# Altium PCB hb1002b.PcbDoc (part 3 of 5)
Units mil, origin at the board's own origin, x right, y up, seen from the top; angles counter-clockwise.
Board outline 2756 x 3549 mil, 2 copper layers (Top Layer, Bottom Layer); 120 components, 136 nets, 498 pads, 328 vias.
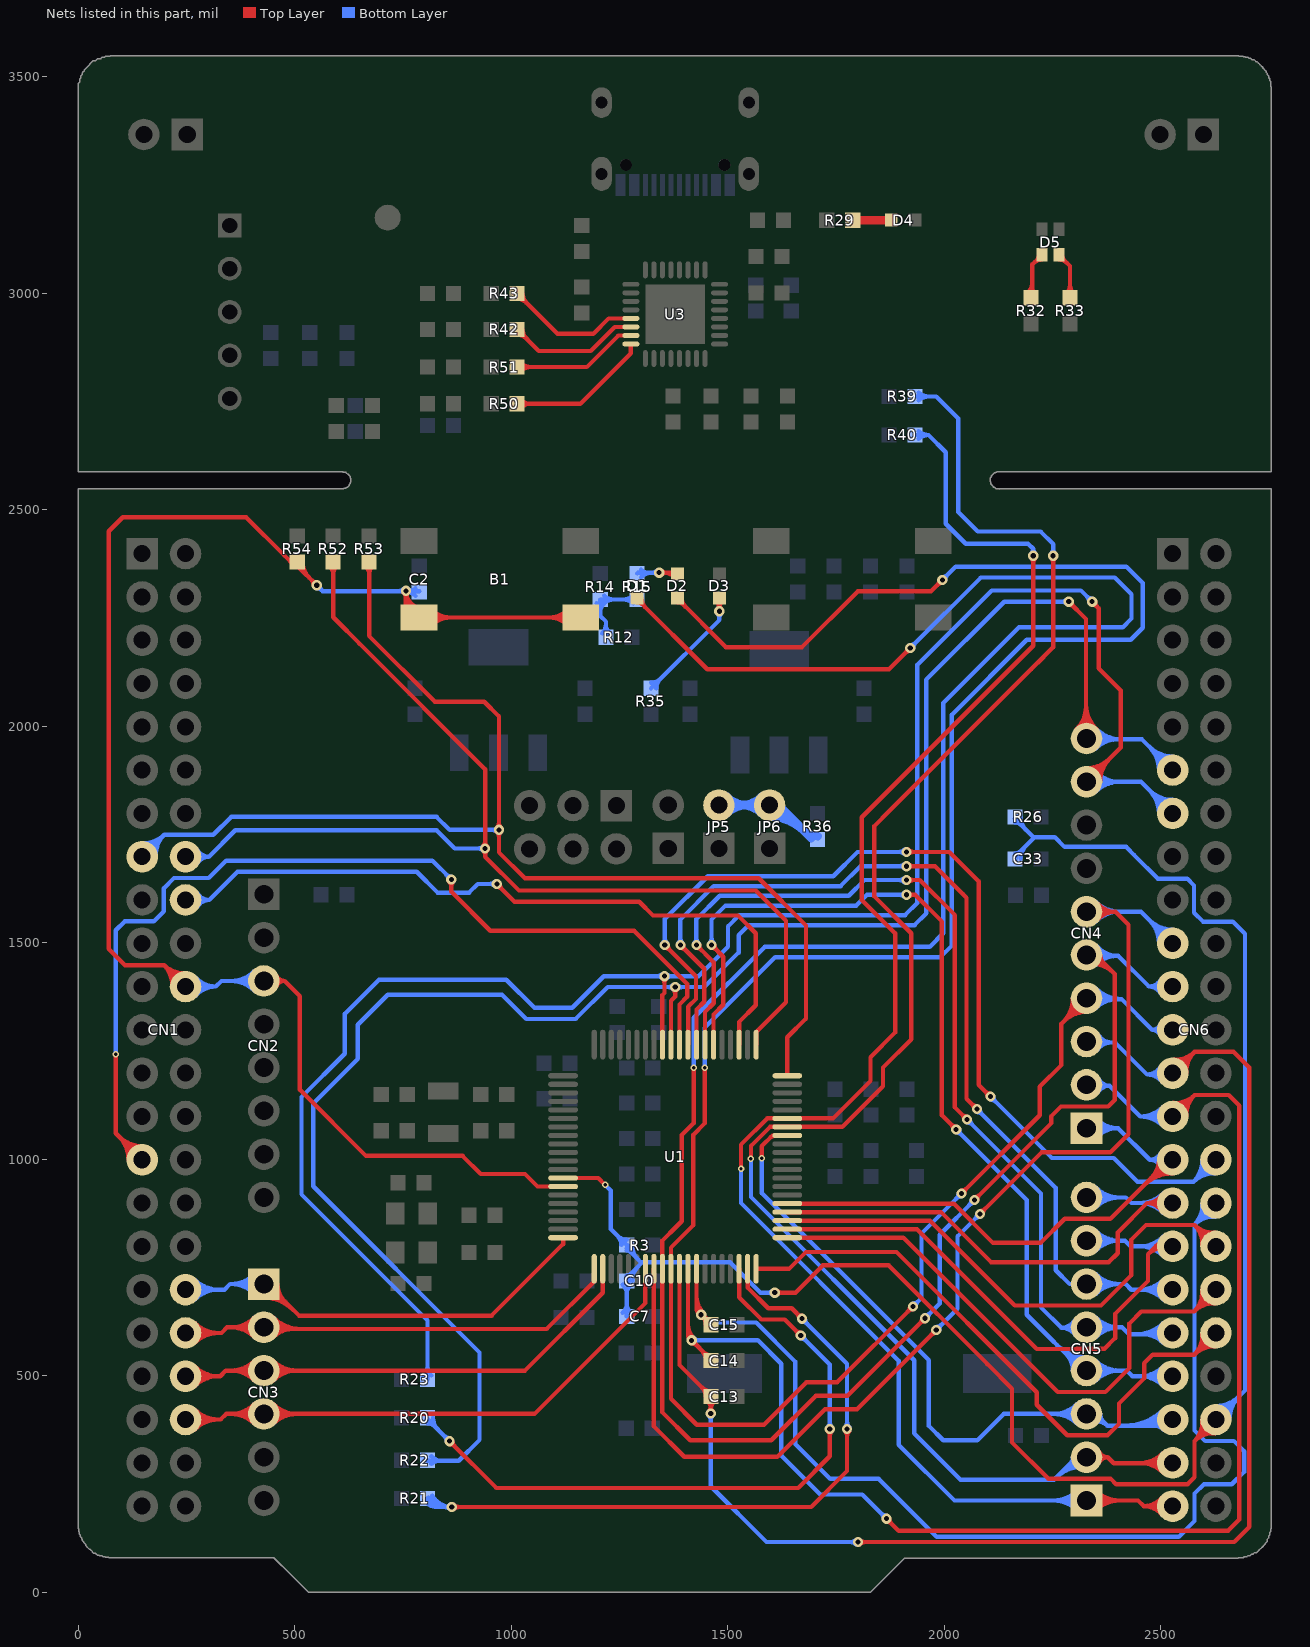
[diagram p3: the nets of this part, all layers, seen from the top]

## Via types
v1: diameter 23.62, hole 11.81, Top Layer to Bottom Layer, tented both sides, 276 vias
v2: diameter 39.37, hole 23.62, Top Layer to Bottom Layer, tented both sides, 27 vias
v3: diameter 15, hole 8, Top Layer to Bottom Layer, tented both sides, 25 vias

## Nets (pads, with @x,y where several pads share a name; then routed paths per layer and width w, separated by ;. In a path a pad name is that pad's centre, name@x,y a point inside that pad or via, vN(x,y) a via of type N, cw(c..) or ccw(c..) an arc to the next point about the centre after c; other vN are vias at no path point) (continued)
NetD2_1: D2.1 R15.1 | length 228.8
  Top Layer w10: v1(1342,2355) D2.1@1381,2355 ; v1@1346.82,2350.18 cw(c1358.44,2338.56) 1358.44,2355 cw(c1358.44,2371.44) v1@1346.82,2359.82 ; v1@1352.62,2355 cw(c1352.62,2320.62) D2.1@1376.93,2344.93 ; 1367.1,2355 ccw(c1367.1,2368.9) D2.1@1376.93,2359.07 ; D2.1@1384,2351 D2.1@1384,2352
  Bottom Layer w10: R15.1@1291,2353 1293,2355 v1(1342,2355) ; R15.1@1299.84,2344.16 cw(c1326.01,2318) 1326.01,2355 ; R15.1@1299.84,2361.84 ccw(c1316.35,2378.35) 1316.35,2355 ; v1@1337.18,2350.18 ccw(c1325.56,2338.56) 1325.56,2355 ccw(c1325.56,2371.44) v1@1337.18,2359.82
NetD3_1: D3.1 R35.1 | length 410.4
  Top Layer w10: D3.1@1473.93,2289.93 cw(c1456.86,2272.86) 1481,2272.86 cw(c1505.14,2272.86) D3.1@1488.07,2289.93 ; v1@1476.18,2270.82 ccw(c1464.56,2282.44) 1481,2282.44 ccw(c1497.44,2282.44) v1@1485.82,2270.82 ; v1(1481,2266) D3.1@1481,2297
  Bottom Layer w10: R35.1@1323,2088 1481,2246 v1@1481,2265 ; R35.1@1323,2100.5 ccw(c1323,2130.68) 1344.34,2109.34 ccw(c1365.68,2088) R35.1@1335.5,2088 ; v1@1476.18,2261.18 cw(c1464.56,2249.56) 1481,2249.56 cw(c1497.44,2249.56) v1@1485.82,2261.18
NetD4_1: D4.1 R29.2 | length 117.4
  Top Layer w20: R29.2@1789,3169 D4.1@1878,3169 ; R29.2@1794.3,3163.7 cw(c1807.11,3150.89) 1807.11,3169 cw(c1807.11,3187.11) R29.2@1794.3,3174.3
NetD5_1: D5.1 R32.2 | length 188.1
  Top Layer w10: R32.2@2192.16,2998.84 ccw(c2163.58,3027.42) 2204,3027.42 ; R32.2@2204,2987 2204,3067 D5.1@2226,3089 ; 2204,3012.94 ccw(c2223.94,3012.94) R32.2@2209.84,2998.84 ; 2207.65,3070.65 cw(c2226,3052.3) D5.1@2226,3078.25 ; D5.1@2214.78,3077.78 ccw(c2206.51,3086.05) D5.1@2218.2,3086.05
NetD5_3: D5.3 R33.2 | length 186.6
  Top Layer w10: D5.3@2265.37,3078.25 cw(c2265.37,3052.3) 2283.72,3070.65 ; D5.3@2265.37,3089 2291,3063.37 R33.2@2291,2990 ; D5.3@2273.17,3086.05 ccw(c2284.86,3086.05) D5.3@2276.59,3077.78 ; R33.2@2282.16,2998.84 ccw(c2260.82,3020.18) 2291,3020.18 ccw(c2321.18,3020.18) R33.2@2299.84,2998.84
NetJP5_2: JP5.2 JP6.2 R36.1 | length 617.7
  Bottom Layer w20: JP5.2@1480,1818 JP6.2@1597,1818 JP6.2@1612,1818 ; JP5.2@1498.68,1799.32 cw(c1543.78,1754.22) 1543.78,1818 cw(c1543.78,1881.78) JP5.2@1498.68,1836.68 ; JP6.2@1578.32,1799.32 ccw(c1533.22,1754.22) 1533.22,1818 ccw(c1533.22,1881.78) JP6.2@1578.32,1836.68 ; JP6.2@1597,1791.58 cw(c1597,1679.52) 1676.24,1758.76 ; JP6.2@1597,1811.58 cw(c1597,1747.81) 1642.1,1792.9 ; JP6.2@1615,1820 R36.1@1693,1742 ; 1674.71,1760.29 ccw(c1708,1793.57) R36.1@1708,1746.5
NetR12_1: R12.1 R14.2 R15.2 | length 367
  Bottom Layer w10: R14.2@1197.16,2284.16 cw(c1175.82,2262.82) 1206,2262.82 cw(c1236.18,2262.82) 1214.84,2284.16 cw(c1236.18,2262.82) 1236.18,2293 cw(c1236.18,2323.18) R14.2@1214.84,2301.84 ; R12.1@1210.16,2214.84 ccw(c1188.82,2236.18) 1219,2236.18 ccw(c1249.18,2236.18) R12.1@1227.84,2214.84 ; R12.1@1219,2206 1219,2242 1206,2255 R14.2@1206,2293 R15.2@1291,2293 ; R15.2@1282.16,2284.16 ccw(c1260.82,2262.82) 1260.82,2293 ccw(c1260.82,2323.18) R15.2@1282.16,2301.84
NetR42_1: R42.1 U3.22 | length 355.7
  Top Layer w10: R42.1@1014,2904.5 cw(c1014,2874.32) 1035.34,2895.66 cw(c1056.68,2917) R42.1@1026.5,2917 ; R42.1@1014,2917 1064,2867 1184,2867 1239.47,2922.47 U3.22@1278.61,2922.47
NetR43_1: R43.1 U3.21 | length 365.1
  Top Layer w10: R43.1@1014,2987.5 cw(c1014,2957.32) 1035.34,2978.66 cw(c1056.68,3000) R43.1@1026.5,3000 ; R43.1@1014,3000 1107,2907 1190,2907 1225.16,2942.16 U3.21@1278.61,2942.16
NetR50_1: R50.1 U3.24 | length 379.8
  Top Layer w10: R50.1@1014,2745 1160,2745 1276.64,2861.64 U3.24@1276.64,2883.1 ; R50.1@1022.84,2736.16 cw(c1044.18,2714.82) 1044.18,2745 cw(c1044.18,2775.18) R50.1@1022.84,2753.84
NetR51_1: R51.1 U3.23 | length 340.2
  Top Layer w10: R51.1@1014,2830 1175,2830 1247.79,2902.79 U3.23@1276.64,2902.79 ; R51.1@1022.84,2821.16 cw(c1044.18,2799.82) 1044.18,2830 cw(c1044.18,2860.18) R51.1@1022.84,2838.84
NRST: B1.3 B1.4 C2.1 CN1.22 CN2.3 R54.2 U1.14 | length 4882.1
  Top Layer w10: CN1.22@216.64,1400.87 ccw(c154.73,1404.56) 198.58,1448.42 ; CN1.22@226.62,1400.28 ccw(c184.42,1402.79) 214.31,1432.69 ccw(c244.21,1462.58) CN1.22@246.72,1420.38 ; CN1.22@246.13,1430.36 cw(c242.44,1492.27) 198.58,1448.42 ; CN1.22@248,1399 198.58,1448.42 ; 378,2483 356,2483 ; CN2.3@429,1412 477,1412 ; CN2.3@457.79,1399.43 cw(c477,1391.04) 477,1412 ; CN2.3@457.79,1424.57 ccw(c477,1432.96) 477,1412 ; R54.2@508.5,2380 ccw(c536.26,2380) 516.63,2360.37 ; R54.2@518.5,2380 ccw(c570.4,2380) 533.7,2343.3 ; v1@544.19,2326 ccw(c527.75,2326) 539.37,2337.63 ccw(c551,2349.25) v1@551,2332.81 ; v1@551.5,2325.5 506,2371 500,2371 475.5,2395.5 388,2483 356,2483 ; v1@752.18,2308.18 cw(c740.56,2296.56) 757,2296.56 cw(c773.44,2296.56) v1@761.82,2308.18 ; 757,2281.41 v1(757,2313) ccw(c798.05,2313) B1.3@783.33,2274.68 ; 757,2283.89 ccw(c786.87,2283.89) B1.3@776.16,2256.01 ; 757,2298.45 ccw(c792.46,2298.45) B1.3@779.74,2265.35 ; B1.3@786.99,2251.42 B1.4@1161.01,2251.42 ; B1.3@810.14,2240.87 cw(c835.61,2215.39) 835.61,2251.42 cw(c835.61,2287.44) B1.3@810.14,2261.97 ; B1.3@817.21,2233.8 cw(c859.76,2191.25) 859.76,2251.42 cw(c859.76,2311.58) B1.3@817.21,2269.04 ; U1.14@1120.14,937.1 1060.9,937.1 1032,966 930,966 888,1008 665,1008 512,1161 512,1377 477,1412 ; B1.4@1130.79,2233.8 ccw(c1088.24,2191.25) 1088.24,2251.42 ccw(c1088.24,2311.58) B1.4@1130.79,2269.04 ; B1.4@1137.86,2240.87 ccw(c1112.39,2215.39) 1112.39,2251.42 ccw(c1112.39,2287.44) B1.4@1137.86,2261.97 ; 198.58,1448.42 108.17,1448.42 70.58,1486 70.58,2450.58 103,2483 356,2483
  Bottom Layer w10: CN1.22@245.83,1400 CN1.22@248,1400 ; CN1.22@248,1399 318,1399 ; CN1.22@264,1384.77 cw(c295.72,1356.55) 295.72,1399 cw(c295.72,1441.45) CN1.22@264,1413.23 ; CN1.22@271.47,1378.12 cw(c318,1336.73) 318,1399 ; CN1.22@271.47,1419.88 ccw(c318,1461.27) 318,1399 ; CN2.3@406.78,1389.78 ccw(c353.15,1336.15) 353.15,1412 ccw(c353.15,1487.85) CN2.3@406.78,1434.22 ; CN2.3@413.86,1396.86 ccw(c377.29,1360.29) 377.29,1412 ccw(c377.29,1463.71) CN2.3@413.86,1427.14 ; CN2.3@429,1412 331,1412 318,1399 ; v1@551,2319.19 cw(c551,2302.75) 562.63,2314.37 cw(c574.25,2326) v1@557.81,2326 ; v1(551,2326) 564.56,2312.44 C2.1@788,2312.44 ; 739.21,2312.44 ccw(c739.21,2330.79) v1@752.18,2317.82 ; 741.91,2312.44 cw(c741.91,2297.91) v1@752.18,2308.18 ; v1@751.93,2312.44 cw(c751.93,2273.93) C2.1@779.16,2301.16 ; v1@761.82,2308.18 cw(c772.09,2297.91) C2.1@772.09,2312.44 ; v1@761.82,2317.82 ccw(c774.79,2330.79) C2.1@774.79,2312.44 ; v1@763.71,2312.44 ccw(c763.71,2334.29) C2.1@779.16,2318.84
PA0: C7.2 C10.2 C33.2 CN6.42 R3.1 R26.1 U1.13 | length 4963.3
  Top Layer w10: U1.13@1120.14,956.79 1181,956.79 1201.21,956.79 v3(1217,941) ; v1(1609,692) 1657,692 1720,755 1872,755 2100,527 2157,470 2157,346 2240.42,262.58 2384.42,262.58 2397.42,249.58 2562.58,249.58 2578.58,265.58 2578.58,349.58 ; v1@1613.82,687.18 cw(c1625.44,675.56) 1625.44,692 cw(c1625.44,708.44) v1@1613.82,696.82 ; CN6.42@2596.64,397.13 cw(c2534.73,393.44) 2578.58,349.58 ; CN6.42@2606.62,397.72 cw(c2564.42,395.21) 2594.31,365.31 cw(c2624.21,335.42) CN6.42@2626.72,377.62 ; CN6.42@2626.13,367.64 ccw(c2622.44,305.73) 2578.58,349.58 ; CN6.42@2628,399 2578.58,349.58
  Bottom Layer w10: v3(1217,941) 1230,928 1230,839 R3.1@1267,802 ; R3.1@1254.5,802 ccw(c1224.32,802) 1245.66,823.34 ccw(c1267,844.68) R3.1@1267,814.5 ; C7.2@1258.16,645.84 ccw(c1236.82,667.18) 1267,667.18 ccw(c1297.18,667.18) C7.2@1275.84,645.84 ; C10.2@1258.16,710.16 cw(c1236.82,688.82) 1267,688.82 cw(c1297.18,688.82) C10.2@1275.84,710.16 ; C10.2@1266,725 1301.5,760.5 ; C7.2@1267,637 C10.2@1267,719 ; C10.2@1267,731.5 ccw(c1267,744.78) C10.2@1276.39,735.39 ; R3.1@1267,789.5 cw(c1267,776.22) R3.1@1276.39,785.61 ; R3.1@1267,795 1300,762 ; C10.2@1269.5,719 cw(c1292.43,719) C10.2@1276.22,735.22 ; R3.1@1269.5,802 ccw(c1292.43,802) R3.1@1276.22,785.78 ; C10.2@1279.5,719 cw(c1326.58,719) 1293.29,752.29 ; R3.1@1279.5,802 ccw(c1326.58,802) 1293.29,768.71 ; v1@1604.18,687.18 ccw(c1592.56,675.56) 1592.56,692 ccw(c1592.56,708.44) v1@1604.18,696.82 ; v1(1609,692) 1576,692 1506,762 1303,762 ; R26.1@2163,1787 2207,1743 ; C33.2@2164,1706.5 ccw(c2164,1724.61) 2176.8,1711.8 ; R26.1@2164,1778.5 cw(c2164,1760.39) 2176.8,1773.2 ; C33.2@2165,1695 2166,1694 2166,1701 2209,1744 2256,1744 2278.42,1721.58 2376,1721.58 ; R26.1@2165,1788 R26.1@2165,1790 ; C33.2@2176.5,1694 cw(c2218.75,1694) 2188.87,1723.87 ; R26.1@2176.5,1791 ccw(c2218.75,1791) 2188.87,1761.13 ; 2396,1721.58 2376,1721.58 ; 2421.42,1720.58 2440,1702 ; CN6.42@2628,399 2695,466 2695,1521 2667,1549 2598,1549 2577.42,1569.58 2577.42,1632.58 2561.58,1648.42 2493.58,1648.42 2440,1702 ; CN6.42@2628,420.42 ccw(c2628,472.12) 2664.56,435.56 ccw(c2701.12,399) CN6.42@2649.42,399 ; CN6.42@2628,430.42 ccw(c2628,506.27) 2681.63,452.63 ccw(c2735.27,399) CN6.42@2659.42,399 ; 1300,762 1301.5,760.5 ; 1300,762 1303,762 ; 1301.5,760.5 1303,762 ; 2376,1721.58 2420.42,1721.58 2440,1702
PA1: CN1.36 CN3.1 U1.20 | length 1628.9
  Top Layer w10: CN3.1@429,680.58 cw(c429,585.42) 496.29,652.71 ; CN3.1@429,690.58 cw(c429,619.56) 479.22,669.78 ; CN3.1@429,700.58 cw(c429,653.71) CN3.1@462.15,686.85 ; CN3.1@429,712 437,712 510,639 955,639 1120.14,804.14 U1.20@1120.14,818.99 ; CN3.1@450.42,712 ccw(c482.81,712) CN3.1@459.9,689.1 ; CN3.1@460.42,712 ccw(c516.95,712) 476.98,672.02
  Bottom Layer w10: CN1.36@248,699 338,699 351,712 CN3.1@429,712 ; CN1.36@263.14,683.86 cw(c299.71,647.29) 299.71,699 cw(c299.71,750.71) CN1.36@263.14,714.14 ; CN1.36@270.22,676.78 cw(c323.85,623.15) 323.85,699 cw(c323.85,774.85) CN1.36@270.22,721.22 ; CN3.1@406.78,689.78 ccw(c353.15,636.15) 353.15,712 ccw(c353.15,787.85) CN3.1@406.78,734.22 ; CN3.1@413.86,696.86 ccw(c377.29,660.29) 377.29,712 ccw(c377.29,763.71) CN3.1@413.86,727.14
PA2: CN1.38 CN3.2 U1.21 | length 1659.2
  Top Layer w10: CN1.38@248,599 331,599 344,612 CN3.2@429,612 433,608 1082,608 1191.99,717.99 U1.21@1191.99,747.14 ; CN1.38@263.14,583.86 cw(c299.71,547.29) 299.71,599 cw(c299.71,650.71) CN1.38@263.14,614.14 ; CN1.38@270.22,576.78 cw(c323.85,523.15) 323.85,599 cw(c323.85,674.85) CN1.38@270.22,621.22 ; CN3.2@406.78,589.78 ccw(c353.15,536.15) 353.15,612 ccw(c353.15,687.85) CN3.2@406.78,634.22 ; CN3.2@413.86,596.86 ccw(c377.29,560.29) 377.29,612 ccw(c377.29,663.71) CN3.2@413.86,627.14 ; CN3.2@437.07,620.07 ccw(c466.22,649.22) 466.22,608 ; CN3.2@444.14,596.86 cw(c471.05,569.95) 471.05,608 ; CN3.2@444.14,627.14 ccw(c490.36,673.36) 490.36,608 ; CN3.2@451.22,589.78 cw(c495.19,545.81) 495.19,608 ; CN3.2@451.22,634.22 ccw(c514.5,697.5) 514.5,608
PA3: CN1.40 CN3.3 U1.22 | length 1700
  Top Layer w10: CN1.40@248,499 328,499 341,512 CN3.3@429,512 1032,512 1211.68,691.68 U1.22@1211.68,747.14 ; CN1.40@263.14,483.86 cw(c299.71,447.29) 299.71,499 cw(c299.71,550.71) CN1.40@263.14,514.14 ; CN1.40@270.22,476.78 cw(c323.85,423.15) 323.85,499 cw(c323.85,574.85) CN1.40@270.22,521.22 ; CN3.3@406.78,489.78 ccw(c353.15,436.15) 353.15,512 ccw(c353.15,587.85) CN3.3@406.78,534.22 ; CN3.3@413.86,496.86 ccw(c377.29,460.29) 377.29,512 ccw(c377.29,563.71) CN3.3@413.86,527.14 ; CN3.3@444.14,496.86 cw(c480.71,460.29) 480.71,512 cw(c480.71,563.71) CN3.3@444.14,527.14 ; CN3.3@451.22,489.78 cw(c504.85,436.15) 504.85,512 cw(c504.85,587.85) CN3.3@451.22,534.22
PA4: CN1.42 CN3.4 U1.27 | length 1853.7
  Top Layer w10: CN1.42@248,399 329,399 342,412 CN3.4@429,412 1054,412 1310.1,668.1 U1.27@1310.1,747.14 ; CN1.42@263.14,383.86 cw(c299.71,347.29) 299.71,399 cw(c299.71,450.71) CN1.42@263.14,414.14 ; CN1.42@270.22,376.78 cw(c323.85,323.15) 323.85,399 cw(c323.85,474.85) CN1.42@270.22,421.22 ; CN3.4@406.78,389.78 ccw(c353.15,336.15) 353.15,412 ccw(c353.15,487.85) CN3.4@406.78,434.22 ; CN3.4@413.86,396.86 ccw(c377.29,360.29) 377.29,412 ccw(c377.29,463.71) CN3.4@413.86,427.14 ; CN3.4@444.14,396.86 cw(c480.71,360.29) 480.71,412 cw(c480.71,463.71) CN3.4@444.14,427.14 ; CN3.4@451.22,389.78 cw(c504.85,336.15) 504.85,412 cw(c504.85,487.85) CN3.4@451.22,434.22
PA5: CN4.6 CN6.19 U1.28 | length 3387.7
  Top Layer w10: U1.28@1329.79,747.14 1329.79,383.21 1400,313 1615,313 1725,423 1799,423 v1(1982,606) ; v1@1975.19,606 cw(c1958.75,606) 1970.37,594.37 cw(c1982,582.75) v1@1982,599.19 ; v1(2083,874) 2225,1016 2384,1016 2426,1058 2426,1542 2396,1572 ; v1@2083,880.81 ccw(c2083,897.25) 2094.63,885.63 ccw(c2106.25,874) v1@2089.81,874 ; CN4.6@2328,1570 CN4.6@2329,1570 ; CN4.6@2329,1572 2396,1572 ; CN4.6@2345.47,1558.3 cw(c2374.67,1534.01) 2374.67,1572 cw(c2374.67,1609.99) CN4.6@2345.47,1585.7 ; CN4.6@2353.15,1551.91 cw(c2396,1516.27) 2396,1572 ; CN4.6@2353.15,1592.09 ccw(c2396,1627.73) 2396,1572
  Bottom Layer w10: v1(1982,606) 2031,655 2031,822 v1(2083,874) ; v1@1982,612.81 ccw(c1982,629.25) 1993.63,617.63 ccw(c2005.25,606) v1@1988.81,606 ; v1@2076.19,874 cw(c2059.75,874) 2071.37,862.37 cw(c2083,850.75) v1@2083,867.19 ; CN4.6@2329,1572 2455,1572 CN6.19@2528,1499 ; CN4.6@2344.14,1556.86 cw(c2380.71,1520.29) 2380.71,1572 cw(c2380.71,1623.71) CN4.6@2344.14,1587.14 ; CN4.6@2351.22,1549.78 cw(c2404.85,1496.15) 2404.85,1572 cw(c2404.85,1647.85) CN4.6@2351.22,1594.22 ; CN6.19@2496.58,1499 ccw(c2420.73,1499) 2474.37,1552.63 ccw(c2528,1606.27) CN6.19@2528,1530.42 ; CN6.19@2506.58,1499 ccw(c2454.88,1499) 2491.44,1535.56 ccw(c2528,1572.12) CN6.19@2528,1520.42
PA6: CN4.5 CN6.21 D1.2 U1.29 | length 6754
  Top Layer w10: D1.2@1291,2287 cw(c1291,2270.1) D1.2@1302.95,2282.05 ; D1.2@1291,2297 1291,2294 1453,2132 1873,2132 v1(1922,2181) ; D1.2@1301,2297 ccw(c1332.39,2297) 1310.19,2274.81 ; 1389,852 1382.5,845.5 ; v3@1421.5,1211 1421.5,1083.5 1394,1056 1394,857 1382.5,845.5 ; v1@1915.19,2181 cw(c1898.75,2181) 1910.37,2169.37 cw(c1922,2157.75) v1@1922,2174.19 ; v1@1949.19,633 cw(c1932.75,633) 1944.37,621.37 cw(c1956,609.75) v1@1956,626.19 ; v1(1956,633) 1777,454 1704,454 1601,351 1414,351 1349.47,415.53 U1.29@1349.47,747.14 1349.47,812.47 1382.5,845.5 ; v1(2070,906) 2247.8,1083.8 2247.8,1099.8 2270,1122 2379,1122 2394,1137 2394,1428 2352,1470 CN4.5@2328,1470 ; v1@2070,912.81 ccw(c2070,929.25) 2081.63,917.63 ccw(c2093.25,906) v1@2076.81,906 ; CN4.5@2330.67,1460.71 cw(c2338.53,1407.73) 2376.4,1445.6 ; CN4.5@2332.14,1450.81 cw(c2342.16,1383.26) 2390.45,1431.55 ; CN4.5@2360.42,1472 ccw(c2385.57,1472) 2367.78,1454.22
  Bottom Layer w10: v3(1422,1211.65) 1422,1327 1586.19,1491.19 1967.19,1491.19 1998,1522 1998,2054 2173,2229 2413,2229 2433,2249 2433,2305 2394,2344 2085,2344 v1(1922,2181) ; v1@1922,2187.81 ccw(c1922,2204.25) 1933.63,2192.63 ccw(c1945.25,2181) v1@1928.81,2181 ; v1(1956,633) 1990,667 1990,826 v1(2070,906) ; v1@1956,639.81 ccw(c1956,656.25) 1967.63,644.63 ccw(c1979.25,633) v1@1962.81,633 ; v1@2063.19,906 cw(c2046.75,906) 2058.37,894.37 cw(c2070,882.75) v1@2070,899.19 ; CN4.5@2328,1470 2402,1470 ; CN4.5@2344.14,1456.86 cw(c2375.88,1425.12) 2375.88,1470 ; CN4.5@2345.21,1486 ccw(c2380.15,1516.16) 2380.15,1470 ; CN4.5@2351.22,1449.78 cw(c2400.02,1400.98) 2400.02,1470 ; CN4.5@2352.78,1492.53 ccw(c2402,1535.02) 2402,1470 ; CN6.21@2500.94,1383.04 ccw(c2473,1366.57) 2473,1399 ; CN6.21@2500.94,1414.96 cw(c2473,1431.43) 2473,1399 ; CN6.21@2509.55,1388.12 ccw(c2490.51,1376.89) 2490.51,1399 ccw(c2490.51,1421.11) CN6.21@2509.55,1409.88 ; CN6.21@2528,1399 2473,1399 ; 2402,1470 2473,1399
PA7: CN4.4 CN6.23 D2.2 U1.30 | length 6379.1
  Top Layer w10: D2.2@1384,2287 cw(c1384,2267.69) 1397.66,2281.34 ; D2.2@1384,2297 1384,2295 1496,2183 1672,2183 1801,2312 1970,2312 v1(1996,2338) ; D2.2@1394,2297 ccw(c1422.97,2297) 1402.49,2276.51 ; v3@1447,1211 1447,1083 1421,1057 1421,848 1369.16,796.16 U1.30@1369.16,747.14 1369.16,446.84 1429,387 1584,387 1682,485 1753,485 v1(1928,660) ; v1@1921.19,660 cw(c1904.75,660) 1916.37,648.37 cw(c1928,636.75) v1@1928,653.19 ; v1@1989.19,2338 cw(c1972.75,2338) 1984.37,2326.37 cw(c1996,2314.75) v1@1996,2331.19 ; v1(2040,921) 2221,1102 2221,1168 2271,1218 2271,1313 CN4.4@2328,1370 ; v1@2040,927.81 ccw(c2040,944.25) 2051.63,932.63 ccw(c2063.25,921) v1@2046.81,921 ; 2274.66,1316.66 ccw(c2219.32,1372) CN4.4@2297.58,1372 ; 2277.07,1319.07 cw(c2329,1267.15) CN4.4@2329,1340.58 ; 2291.73,1333.73 ccw(c2253.46,1372) CN4.4@2307.58,1372 ; 2294.15,1336.15 cw(c2329,1301.29) CN4.4@2329,1350.58
  Bottom Layer w10: v3(1447,1211.65) 1447,1304 1610,1467 1991,1467 2018,1494 2018,2027 2191,2200 2431,2200 2459,2228 2459,2331 2421,2369 2027,2369 v1(1996,2338) ; v1(1928,660) 1948,680 1948,829 v1(2040,921) ; v1@1928,666.81 ccw(c1928,683.25) 1939.63,671.63 ccw(c1951.25,660) v1@1934.81,660 ; v1@1996,2344.81 ccw(c1996,2361.25) 2007.63,2349.63 ccw(c2019.25,2338) v1@2002.81,2338 ; v1@2033.19,921 cw(c2016.75,921) 2028.37,909.37 cw(c2040,897.75) v1@2040,914.19 ; CN4.4@2328,1370 2410,1370 2481,1299 ; CN4.4@2328,1390 CN4.4@2336,1390 ; CN4.4@2344.14,1356.86 cw(c2375.88,1325.12) 2375.88,1370 ; CN4.4@2344.14,1387.14 ccw(c2385.53,1428.53) 2385.53,1370 ; CN4.4@2351.22,1349.78 cw(c2400.02,1300.98) 2400.02,1370 ; CN4.4@2351.22,1394.22 ccw(c2409.68,1452.68) 2409.68,1370 ; CN6.23@2498.97,1286.99 ccw(c2481,1279.56) 2481,1299 ; CN6.23@2498.97,1311.01 cw(c2481,1318.44) 2481,1299 ; CN6.23@2513,1299 CN6.23@2528,1299 2481,1299
PA8: CN5.8 CN6.31 U1.44 | length 1760.7
  Top Layer w10: U1.44@1637.86,878.05 1992.95,878.05 2108.42,762.58 2380.58,762.58 2401,783 2401,831 2469,899 ; CN6.31@2501.93,881.46 ccw(c2469,859.31) 2469,899 ; CN6.31@2501.93,916.54 cw(c2469,938.69) 2469,899 ; CN6.31@2510.23,887.05 ccw(c2487.78,871.95) 2487.78,899 ccw(c2487.78,926.05) CN6.31@2510.23,910.95 ; CN6.31@2527,898 CN6.31@2528,899 2469,899
  Bottom Layer w10: CN5.8@2328,912 2420,912 2433,899 CN6.31@2528,899 ; CN5.8@2344.14,896.86 cw(c2380.71,860.29) 2380.71,912 cw(c2380.71,963.71) CN5.8@2344.14,927.14 ; CN5.8@2351.22,889.78 cw(c2404.85,836.15) 2404.85,912 cw(c2404.85,987.85) CN5.8@2351.22,934.22 ; CN6.31@2505.78,876.78 ccw(c2452.15,823.15) 2452.15,899 ccw(c2452.15,974.85) CN6.31@2505.78,921.22 ; CN6.31@2512.86,883.86 ccw(c2476.29,847.29) 2476.29,899 ccw(c2476.29,950.71) CN6.31@2512.86,914.14
PA9: CN4.1 CN6.29 U1.45 | length 1760.7
  Top Layer w10: U1.45@1637.86,897.73 2022.27,897.73 2113,807 2223,807 2278.58,862.58 2348.47,862.58 ; CN4.1@2328,1089 2328,1090 CN4.1@2351,1090 ; 2360.58,862.58 2348.47,862.58 ; 2461.64,940.1 cw(c2528,873.73) CN6.29@2528,967.58 ; 2478.71,957.17 cw(c2528,907.88) CN6.29@2528,977.58 ; 2479.64,958.1 ccw(c2438.73,999) CN6.29@2496.58,999 ; 2495.78,974.24 cw(c2528,942.02) CN6.29@2528,987.58 ; 2496.71,975.17 ccw(c2472.88,999) CN6.29@2506.58,999 ; CN6.29@2528,999 2520.54,999 2384.13,862.58 2348.47,862.58
  Bottom Layer w10: CN4.1@2328,1070 CN4.1@2329,1070 ; CN4.1@2329,1072 2402,1072 ; CN4.1@2344.55,1057.28 cw(c2378.76,1024.9) 2378.76,1072 cw(c2378.76,1119.1) CN4.1@2344.55,1086.72 ; CN4.1@2351.82,1050.4 cw(c2402,1002.91) 2402,1072 ; CN4.1@2351.82,1093.6 ccw(c2402,1141.09) 2402,1072 ; CN6.29@2500.44,983.92 ccw(c2475,970.01) 2475,999 ; CN6.29@2500.44,1014.08 cw(c2475,1027.99) 2475,999 ; CN6.29@2528,999 2475,999 ; 2402,1072 2475,999
PA10: CN5.3 CN6.41 U1.53 | length 2102.3
  Top Layer w10: v3(1579,1002) 1579,1030.53 1603.68,1055.21 U1.53@1637.86,1055.21 ; 1598.15,1049.68 cw(c1609.31,1038.51) U1.53@1609.31,1054.31
  Bottom Layer w10: v3(1579,1002) 1579,922 1965,536 1965,384 1998,351 2077,351 2138,412 CN5.3@2329,412 2350,412 2377,385 2490,385 2504,399 CN6.41@2528,399 ; CN5.3@2306.78,389.78 ccw(c2253.15,336.15) 2253.15,412 ccw(c2253.15,487.85) CN5.3@2306.78,434.22 ; CN5.3@2313.86,396.86 ccw(c2277.29,360.29) 2277.29,412 ccw(c2277.29,463.71) CN5.3@2313.86,427.14 ; CN5.3@2333.56,401.53 cw(c2345.55,374.05) 2366.75,395.25 ; CN5.3@2337.56,392.37 cw(c2351.85,359.6) 2377.12,384.88 ; CN5.3@2360.42,412 ccw(c2385.57,412) 2367.78,394.22 ; 2418.35,385 ccw(c2418.35,508.65) CN6.41@2505.78,421.22 ; 2442.5,385 ccw(c2442.5,484.5) CN6.41@2512.86,414.14 ; 2466.64,385 ccw(c2466.64,460.36) CN6.41@2519.93,407.07 ; 2485.95,385 cw(c2485.95,356.95) CN6.41@2505.78,376.78 ; 2490.78,385 ccw(c2490.78,436.22) CN6.41@2527,400
PA11: CN5.2 CN6.43 R39.2 U1.54 | length 4615.2
  Top Layer w10: v3(1554,1001) 1554,1030.99 1597.91,1074.9 U1.54@1637.86,1074.9 1764.9,1074.9 1859,1169 1859,1212 1924,1277 1924,1522 1839,1607 1839,1770 1873.5,1804.5 ; 1859,1790 1873.5,1804.5 ; 2219,2150 2201,2132 ; 2230,2161 2201,2132 ; v1@2247.18,2389.18 cw(c2235.56,2377.56) 2252,2377.56 cw(c2268.44,2377.56) v1@2256.82,2389.18 ; v1(2252,2394) 2252,2183 2201,2132 ; CN5.2@2328,312 CN5.2@2329,312 2378,312 ; CN5.2@2357.55,298.89 cw(c2378,289.5) 2378,312 ; CN5.2@2357.55,325.11 ccw(c2378,334.5) 2378,312 ; 2450.19,298.19 ccw(c2450.19,376.81) CN6.43@2505.78,321.22 ; 2454.11,298.19 cw(c2454.11,225.11) CN6.43@2505.78,276.78 ; 2474.34,298.19 ccw(c2474.34,352.66) CN6.43@2512.86,314.14 ; 2478.25,298.19 cw(c2478.25,249.25) CN6.43@2512.86,283.86 ; CN6.43@2499.21,286.43 ccw(c2480,278.04) 2480,299 ; CN6.43@2499.21,311.57 cw(c2480,319.96) 2480,299 ; CN6.43@2528,299 2490,299 ; 1873.5,1804.5 2201,2132 ; 2378,312 2391.81,298.19 2489.19,298.19 2490,299 ; 2480,299 2490,299
  Bottom Layer w10: v3(1554,1001) 1554,913 1931,536 1931,367 2038,260 2254,260 2306,312 CN5.2@2328,312 ; R39.2@1933,2762 1982,2762 2033,2711 2033,2495 2078,2450 2223,2450 2252,2421 v1(2252,2394) ; R39.2@1941.84,2753.16 cw(c1963.18,2731.82) 1963.18,2762 cw(c1963.18,2792.18) R39.2@1941.84,2770.84 ; v1@2247.18,2398.82 ccw(c2235.56,2410.44) 2252,2410.44 ccw(c2268.44,2410.44) v1@2256.82,2398.82 ; 2258.23,264.23 cw(c2322.33,200.14) CN5.2@2327.72,290.62 ; 2273.96,279.96 cw(c2324.1,229.83) CN5.2@2328.32,300.6 ; 2289.69,295.69 cw(c2325.87,259.51) CN5.2@2328.92,310.59 ; 2291.63,297.63 ccw(c2277.26,312) CN5.2@2297.58,312
PA12: CN5.1 CN6.45 R40.2 U1.55 | length 4541.6
  Top Layer w10: v3(1531,978) 1531,1034 1591.58,1094.58 U1.55@1637.86,1094.58 1743.58,1094.58 1830,1181 1830,1236 1887,1293 1887,1522 1810,1599 1810,1790 1844.5,1824.5 ; 1830,1810 1844.5,1824.5 ; 2184,2164 2175,2155 ; v1@2201.18,2389.18 cw(c2189.56,2377.56) 2206,2377.56 cw(c2222.44,2377.56) v1@2210.82,2389.18 ; v1(2206,2394) 2206,2186 2175,2155 ; CN5.1@2332,212 2448,212 2461,199 ; CN5.1@2344.14,196.86 cw(c2380.71,160.29) 2380.71,212 cw(c2380.71,263.71) CN5.1@2344.14,227.14 ; CN5.1@2351.22,189.78 cw(c2404.85,136.15) 2404.85,212 cw(c2404.85,287.85) CN5.1@2351.22,234.22 ; CN6.45@2503.85,178.91 ccw(c2461,143.27) 2461,199 ; CN6.45@2503.85,219.09 cw(c2461,254.73) 2461,199 ; CN6.45@2511.53,185.3 ccw(c2482.33,161.01) 2482.33,199 ccw(c2482.33,236.99) CN6.45@2511.53,212.7 ; CN6.45@2528,199 2461,199 ; 1844.5,1824.5 2175,2155
  Bottom Layer w10: v3(1531,978) 1531,899 1895,535 1895,341 2024,212 CN5.1@2328,212 ; R40.2@1933,2673 1964,2673 2004,2633 2004,2468 2050,2422 2194,2422 2206,2410 ; R40.2@1941.84,2664.16 cw(c1963.18,2642.82) 1963.18,2673 cw(c1963.18,2703.18) R40.2@1941.84,2681.84 ; v1@2201.28,2398.91 ccw(c2190.61,2410) 2206,2410 ; 2201.45,2414.55 cw(c2182.61,2395.71) v1@2209.18,2393.77 ; v1(2206,2394) 2206,2410 ; v1@2210.72,2398.91 cw(c2221.39,2410) 2206,2410 ; CN5.1@2306.78,189.78 ccw(c2253.15,136.15) 2253.15,212 ccw(c2253.15,287.85) CN5.1@2306.78,234.22 ; CN5.1@2313.86,196.86 ccw(c2277.29,160.29) 2277.29,212 ccw(c2277.29,263.71) CN5.1@2313.86,227.14 ; CN5.1@2326,210 CN5.1@2328,212 ; CN5.1@2329,212 CN5.1@2328,212
PA13: CN1.15 R53.2 U1.60 | length 3178.3
  Top Layer w10: R53.2@663.16,2371.16 cw(c641.82,2349.82) 672,2349.82 cw(c702.18,2349.82) R53.2@680.84,2371.16 ; R53.2@672,2371 672,2209 824,2057 938,2057 972,2023 v1(972,1761) 972,1709 1032,1649 1572,1649 1681,1540 1681,1325 1637.86,1281.86 U1.60@1637.86,1193.01 ; v1@967.18,1756.18 cw(c955.56,1744.56) 972,1744.56 cw(c988.44,1744.56) v1@976.82,1756.18 ; v1@967.18,1765.82 ccw(c955.56,1777.44) 972,1777.44 ccw(c988.44,1777.44) v1@976.82,1765.82
  Bottom Layer w10: CN1.15@148,1699 198.58,1749.58 ; CN1.15@148.91,1720.4 ccw(c150.8,1765.16) 182.48,1733.48 ccw(c214.16,1701.8) CN1.15@169.4,1699.91 ; CN1.15@149.33,1730.39 ccw(c152.11,1796.05) 198.58,1749.58 ; CN1.15@179.39,1700.33 cw(c245.05,1703.11) 198.58,1749.58 ; v1@967.18,1756.18 ccw(c955.56,1744.56) 955.56,1761 ccw(c955.56,1777.44) v1@967.18,1765.82 ; v1@971,1761 858,1761 828,1791 353.42,1791 312,1749.58 198.58,1749.58
PA14: CN1.16 R52.2 U1.61 | length 2878.3
  Top Layer w10: R52.2@580.16,2371.16 cw(c558.82,2349.82) 589,2349.82 cw(c619.18,2349.82) R52.2@597.84,2371.16 ; R52.2@589,2371 589,2252 655.5,2185.5 ; 649.5,2191.5 655.5,2185.5 ; v1@935.18,1713.18 cw(c923.56,1701.56) 940,1701.56 cw(c956.44,1701.56) v1@944.82,1713.18 ; v1@935.18,1722.82 ccw(c923.56,1734.44) 940,1734.44 ccw(c956.44,1734.44) v1@944.82,1722.82 ; U1.61@1566.01,1264.86 1566.01,1294.01 1635,1363 1635,1463 ; 1635,1450 1635,1463 ; 655.5,2185.5 940,1901 v1(940,1718) 940,1699 1018.19,1620.81 1565.19,1620.81 1635,1551 1635,1463
  Bottom Layer w10: CN1.16@248,1699 302,1699 ; CN1.16@266.62,1688.42 cw(c284.81,1678.08) 284.81,1699 cw(c284.81,1719.92) CN1.16@266.62,1709.58 ; CN1.16@275.31,1683.47 cw(c302,1668.31) 302,1699 ; CN1.16@275.31,1714.53 ccw(c302,1729.69) 302,1699 ; v1@935.18,1713.18 ccw(c923.56,1701.56) 923.56,1718 ccw(c923.56,1734.44) v1@935.18,1722.82 ; v1(940,1718) 870,1718 828,1760 363,1760 302,1699
PA15: CN1.18 U1.63 | length 1902.2
  Top Layer w10: v1@967,1629.19 cw(c967,1612.75) 978.63,1624.37 cw(c990.25,1636) v1@973.81,1636 ; v1(967,1636) 1008,1595 1295.91,1595 1327.91,1563 1524,1563 1565,1522 1565,1496 ; U1.63@1526.64,1264.86 1526.64,1317.27 1565,1355.63 1565,1374 ; 1565,1357.63 1565,1374 ; 1565,1520 1565,1496 ; 1565,1374 1565,1496
  Bottom Layer w8: CN1.18@228,1599 CN1.18@232.63,1599
  Bottom Layer w10: CN1.18@248,1599 303,1599 ; CN1.18@266.45,1588.12 cw(c285.49,1576.89) 285.49,1599 cw(c285.49,1621.11) CN1.18@266.45,1609.88 ; CN1.18@275.06,1583.04 cw(c303,1566.57) 303,1599 ; CN1.18@275.06,1614.96 ccw(c303,1631.43) 303,1599 ; v1@962.18,1631.18 ccw(c950.56,1619.56) 950.56,1636 ccw(c950.56,1652.44) v1@962.18,1640.82 ; v1(967,1636) 923,1636 903,1616 830,1616 782,1664 368,1664 303,1599
PB0: C13.1 CN4.3 CN6.25 U1.31 | length 3980.8
  Top Layer w10: U1.31@1388.84,747.14 1388.84,525.16 C13.1@1462,452 1461,451 v1(1461,413) ; C13.1@1449.5,452 ccw(c1419.32,452) 1440.66,473.34 ccw(c1462,494.68) C13.1@1462,464.5 ; C13.1@1453.16,443.16 cw(c1434.23,424.23) v1@1461,424.23 ; v1@1456.18,417.82 ccw(c1444.56,429.44) 1461,429.44 ccw(c1477.44,429.44) v1@1465.82,417.82 ; v1@1461,419.41 cw(c1494.59,419.41) C13.1@1470.84,443.16 ; v1(1801,116) 2670,116 2705,151 2705,1212 2668.58,1248.42 2578.58,1248.42 ; v1@1805.82,111.18 cw(c1817.44,99.56) 1817.44,116 cw(c1817.44,132.44) v1@1805.82,120.82 ; CN6.25@2528,1199 2529.17,1199 2578.58,1248.42 ; CN6.25@2529.5,1220.36 ccw(c2532.53,1263.45) 2563.07,1232.91 ; CN6.25@2530.21,1230.34 ccw(c2534.57,1292.42) 2578.58,1248.41 ; CN6.25@2549.41,1199.67 cw(c2593.27,1201.04) 2562.24,1232.07 ; CN6.25@2559.4,1199.98 cw(c2624.96,1202.04) 2578.58,1248.41
  Bottom Layer w10: v1@1456.18,408.18 cw(c1444.56,396.56) 1461,396.56 cw(c1477.44,396.56) v1@1465.82,408.18 ; v1(1461,413) 1461,245 1590,116 v1(1801,116) ; v1@1796.18,111.18 ccw(c1784.56,99.56) 1784.56,116 ccw(c1784.56,132.44) v1@1796.18,120.82 ; CN4.3@2328,1270 2386,1270 ; CN4.3@2346.46,1259.59 cw(c2366.62,1245.26) 2366.62,1270 ; CN4.3@2347.69,1282.46 ccw(c2368.94,1294.35) 2368.94,1270 ; CN4.3@2354.61,1253.8 cw(c2386,1231.49) 2386,1270 ; CN4.3@2356.42,1287.34 ccw(c2386,1303.9) 2386,1270 ; 2486.14,1196 ccw(c2486.14,1222.67) CN6.25@2509.36,1209.54 ; 2489.76,1196 cw(c2489.76,1168.52) CN6.25@2511.25,1185.65 ; CN6.25@2500.65,1214.46 cw(c2469,1232.36) 2469,1196 ; CN6.25@2503.43,1179.42 ccw(c2469,1151.97) 2469,1196 ; CN6.25@2528,1199 2525,1196 2469,1196 ; 2386,1270 2395,1270 2469,1196
PB1: C14.1 CN4.2 CN6.27 U1.32 | length 3878.2
  Top Layer w10: 1408.53,594.76 ccw(c1429.76,594.76) v1@1414.75,579.75 ; 1408.53,618.9 ccw(c1453.9,618.9) v1@1421.82,586.82 ; U1.32@1409.31,746.36 U1.32@1408.53,747.14 1408.53,590.47 v1(1417,582) C14.1@1455,544 ; v1@1417,575.19 cw(c1417,558.75) 1428.63,570.37 cw(c1440.25,582) v1@1423.81,582 ; 1439.25,559.75 cw(c1414.49,535) C14.1@1449.5,535 ; 1444.08,554.92 ccw(c1462,572.84) C14.1@1462,547.5 ; v1@1867,163.19 cw(c1867,146.75) 1878.63,158.37 cw(c1890.25,170) v1@1873.81,170 ; v1(1867,170) 1895,142 2656,142 2682,168 2682,213 ; CN6.27@2517,1088 CN6.27@2528,1099 2529.17,1099 2578.58,1148.42 ; CN6.27@2529.5,1120.36 ccw(c2532.53,1163.45) 2563.07,1132.91 ; CN6.27@2530.21,1130.34 ccw(c2534.57,1192.42) 2578.58,1148.41 ; CN6.27@2549.41,1099.67 cw(c2593.27,1101.04) 2562.24,1132.07 ; CN6.27@2559.4,1099.98 cw(c2624.96,1102.04) 2578.58,1148.41 ; 2682,190 2682,213 ; 2578.58,1148.42 2657.58,1148.42 2682,1124 2682,213
  Bottom Layer w10: v1(1417,582) 1570,582 1624,528 1624,316 1714,226 1811,226 v1(1867,170) ; v1@1421.82,577.18 cw(c1433.44,565.56) 1433.44,582 cw(c1433.44,598.44) v1@1421.82,586.82 ; v1@1860.19,170 ccw(c1843.75,170) 1855.37,181.63 ccw(c1867,193.25) v1@1867,176.81 ; CN4.2@2328,1170 2382,1170 ; CN4.2@2348.33,1181.23 ccw(c2366.14,1189.74) 2366.14,1170 ; CN4.2@2355.66,1155.38 cw(c2382,1138.97) 2382,1170 ; CN4.2@2357.35,1185.54 ccw(c2382,1197.32) 2382,1170 ; CN6.27@2505.61,1076.96 ccw(c2453,1025.2) 2453,1099 ; CN6.27@2505.61,1121.04 cw(c2453,1172.8) 2453,1099 ; CN6.27@2512.73,1083.98 ccw(c2476.88,1048.69) 2476.88,1099 ccw(c2476.88,1149.31) CN6.27@2512.73,1114.02 ; CN6.27@2528,1099 2453,1099 ; 2382,1170 2453,1099
PB2: C15.1 CN6.32 U1.33 | length 2888.4
  Top Layer w10: U1.33@1428,746.93 U1.33@1428.21,747.14 1428.21,651.79 C15.1@1462,618 ; 1428.21,659.34 ccw(c1457.34,659.34) v1@1436.75,638.75 ; 1428.21,683.49 ccw(c1481.49,683.49) v1@1443.82,645.82 ; v1@1439,634.19 cw(c1439,617.75) C15.1@1450.62,629.37 ; v1@1445.81,641 ccw(c1462.26,641) C15.1@1450.63,629.37 ; C15.1@1449.5,618 ccw(c1419.32,618) 1440.66,639.34 ccw(c1462,660.68) C15.1@1462,630.5
  Bottom Layer w10: v1@1439,634.19 cw(c1439,617.75) 1450.63,629.37 cw(c1462.25,641) v1@1445.81,641 ; v1(1439,641) 1457,623 1566,623 1656,533 1656,343 1737,262 1849,262 1983,128 2542,128 2578.58,164.58 2578.58,228 2600.17,249.58 2664.58,249.58 2693,278 2693,326 2669.42,349.58 2602.87,349.58 2578.58,373.87 2578.58,849.58 ; CN6.32@2596.64,897.13 cw(c2534.73,893.44) 2578.58,849.58 ; CN6.32@2606.62,897.72 cw(c2564.42,895.21) 2594.31,865.31 cw(c2624.21,835.42) CN6.32@2626.72,877.62 ; CN6.32@2626.13,867.64 ccw(c2622.44,805.73) 2578.58,849.58 ; CN6.32@2628,899 2578.58,849.58
PB3: CN5.4 CN6.39 U1.66 | length 3272.6
  Top Layer w10: v1@1462.5,1495.5 v1@1463,1496 ; v1@1463,1488.19 cw(c1463,1471.75) 1474.63,1483.37 cw(c1486.25,1495) v1@1469.81,1495 ; v1(1463,1495) 1490,1468 1490,1357 1467.58,1334.58 U1.66@1467.58,1264.86 ; v1(1913,1611) 1933,1611 1995,1549 1995,1237 1995,1102 v1(2028,1069) ; v1@1917.82,1606.18 cw(c1929.44,1594.56) 1929.44,1611 cw(c1929.44,1627.44) v1@1917.82,1615.82 ; v1@2021.19,1069 ccw(c2004.75,1069) 2016.37,1080.63 ccw(c2028,1092.25) v1@2028,1075.81
  Bottom Layer w10: v1@1458.18,1499.82 ccw(c1446.56,1511.44) 1463,1511.44 ccw(c1479.44,1511.44) v1@1467.82,1499.82 ; v1(1463,1495) 1463,1554 1495,1586 1797,1586 1822,1611 v1(1913,1611) ; v1@1908.18,1606.18 ccw(c1896.56,1594.56) 1896.56,1611 ccw(c1896.56,1627.44) v1@1908.18,1615.82 ; v1@2028,1062.19 cw(c2028,1045.75) 2039.63,1057.37 cw(c2051.25,1069) v1@2034.81,1069 ; v1(2028,1069) 2191,906 2191,641 2320,512 CN5.4@2328,512 ; 2260,572 ccw(c2329,640.99) CN5.4@2329,543.42 ; 2277.07,554.93 ccw(c2329,606.85) CN5.4@2329,533.42 ; 2281.73,550.27 cw(c2243.46,512) CN5.4@2297.58,512 ; 2294.15,537.85 ccw(c2329,572.71) CN5.4@2329,523.42 ; 2298.8,533.2 cw(c2277.6,512) CN5.4@2307.58,512 ; CN5.4@2344.14,496.86 cw(c2380.71,460.29) 2380.71,512 cw(c2380.71,563.71) CN5.4@2344.14,527.14 ; CN5.4@2346.44,499.56 cw(c2370.58,482.34) 2370.58,512 cw(c2370.58,541.66) CN5.4@2346.44,524.44 ; CN5.4@2351.22,489.78 cw(c2404.85,436.15) 2404.85,512 cw(c2404.85,587.85) CN5.4@2351.22,534.22 ; CN5.4@2354.58,493.76 cw(c2390,468.49) 2390,512 ; CN5.4@2354.58,530.24 ccw(c2390,555.51) 2390,512 ; CN6.39@2505.78,476.78 ccw(c2452.15,423.15) 2452.15,499 ccw(c2452.15,574.85) CN6.39@2505.78,521.22 ; CN6.39@2512.86,483.86 ccw(c2476.29,447.29) 2476.29,499 ccw(c2476.29,550.71) CN6.39@2512.86,514.14 ; CN6.39@2528,499 2435,499 2422,512 CN5.4@2328,512 ; CN5.4@2328,512 2390,512
PB4: CN5.5 CN6.37 U1.67 | length 3285.4
  Top Layer w10: v1@1428,1488.19 cw(c1428,1471.96) 1439.48,1483.44 ; v1(1428,1495) 1428,1494.91 1468,1454.91 1468,1360.46 1447.9,1340.35 U1.67@1447.9,1264.86 ; v1@1434.81,1495 ccw(c1451.47,1495) 1439.69,1483.22 ; v1(1913,1645) 1944,1645 2025,1564 2025,1120 v1@2052,1093 ; v1@1917.82,1640.18 cw(c1929.44,1628.56) 1929.44,1645 cw(c1929.44,1661.44) v1@1917.82,1649.82 ; v1@2046.19,1092 ccw(c2029.75,1092) 2041.37,1103.63 ccw(c2053,1115.25) v1@2053,1098.81
  Bottom Layer w10: v1@1423.18,1499.82 ccw(c1411.56,1511.44) 1428,1511.44 ccw(c1444.44,1511.44) v1@1432.82,1499.82 ; v1(1428,1495) 1428,1555 1482,1609 1780,1609 1816,1645 v1(1913,1645) ; v1@1908.18,1640.18 ccw(c1896.56,1628.56) 1896.56,1645 ccw(c1896.56,1661.44) v1@1908.18,1649.82 ; v1@1912,1642 v1@1913,1641 ; v1@2053,1085.19 cw(c2053,1068.75) 2064.63,1080.37 cw(c2076.25,1092) v1@2059.81,1092 ; v1(2053,1092) 2224,921 2224,658 2271,611 ; 2288.89,611 ccw(c2288.89,636.67) CN5.5@2310.76,623.22 ; 2290.07,611 cw(c2290.07,585.09) CN5.5@2311.38,599.82 ; CN5.5@2302.24,628.46 cw(c2271,647.67) 2271,611 ; CN5.5@2303.15,594.14 ccw(c2271,571.92) 2271,611 ; 2408,612 CN5.5@2329,612 ; 2444.91,596 ccw(c2444.91,682.09) CN6.37@2505.78,621.22 ; 2459.39,596 cw(c2459.39,530.39) CN6.37@2505.78,576.78 ; 2469.05,596 ccw(c2469.05,657.95) CN6.37@2512.86,614.14 ; 2483.54,596 cw(c2483.54,554.54) CN6.37@2512.86,583.86 ; CN6.37@2507,599 CN6.37@2528,599 2525,596 2427,596 2411,612 CN5.5@2329,612 ; 2271,611 2327,611 2328,612 CN5.5@2329,612 ; 2380.71,612 ccw(c2380.71,560.29) 2344.14,596.86 cw(c2380.71,560.29) 2380.71,612 ; 2380.71,612 cw(c2380.71,663.71) 2344.14,627.14 ccw(c2380.71,663.71) 2380.71,612 ; 2404.85,612 ccw(c2404.85,536.15) 2351.22,589.78 cw(c2404.85,536.15) 2404.85,612 ; 2404.85,612 cw(c2404.85,687.85) 2351.22,634.22 ccw(c2404.85,687.85) 2404.85,612
PB5: CN5.6 CN6.35 U1.68 | length 2990.4
  Top Layer w10: v1@1391,1488.19 cw(c1391,1471.75) 1402.63,1483.37 cw(c1414.25,1495) v1@1397.81,1495 ; v1(1391,1495) v1@1394,1492 ; v1@1394,1494 v1@1394,1492 ; U1.68@1428.21,1264.86 1428.21,1346.12 1446,1363.91 1446,1440 v1@1394,1492 ; v1(1913,1677) 1979,1677 2019.5,1636.5 ; v1@1917.82,1672.18 cw(c1929.44,1660.56) 1929.44,1677 cw(c1929.44,1693.44) v1@1917.82,1681.82 ; 2044,1612 2019.5,1636.5 ; 2052,1148 2052,1154 ; v1@2069.19,1116 ccw(c2052.75,1116) 2064.37,1127.63 ccw(c2076,1139.25) v1@2076,1122.81 ; v1@2071.19,1116.81 v1@2074,1114 ; v1(2076,1116) 2052,1140 2052,1154 ; 2019.5,1636.5 2052,1604 2052,1154
  Bottom Layer w10: v1@1386.18,1499.82 ccw(c1374.56,1511.44) 1391,1511.44 ccw(c1407.44,1511.44) v1@1395.82,1499.82 ; v1(1391,1495) 1391,1554 1468,1631 1761,1631 1807,1677 v1(1913,1677) ; v1@1908.18,1672.18 ccw(c1896.56,1660.56) 1896.56,1677 ccw(c1896.56,1693.44) v1@1908.18,1681.82 ; v1@2074,1114 v1@2078,1114 ; v1@2076,1109.19 cw(c2076,1092.75) 2087.63,1104.37 cw(c2099.25,1116) v1@2082.81,1116 ; v1(2076,1116) v1@2078,1114 ; v1@2080.54,1114 v1@2078,1114 ; CN5.6@2329,712 2419.46,712 2432.46,699 CN6.35@2528,699 2484,699 ; CN5.6@2332,716 2328,712 2290,712 2258,744 2258,934 v1@2078,1114 ; CN5.6@2344.14,696.86 cw(c2380.71,660.29) 2380.71,712 cw(c2380.71,763.71) CN5.6@2344.14,727.14 ; CN5.6@2351.22,689.78 cw(c2404.85,636.15) 2404.85,712 cw(c2404.85,787.85) CN5.6@2351.22,734.22 ; CN6.35@2498.28,688.8 ccw(c2484,683.9) 2484,699 ; CN6.35@2498.28,709.2 cw(c2484,714.1) 2484,699 ; CN6.35@2505.78,676.78 ccw(c2452.15,623.15) 2452.15,699 ccw(c2452.15,774.85) CN6.35@2505.78,721.22 ; CN6.35@2512.86,683.86 ccw(c2476.29,647.29) 2476.29,699 ccw(c2476.29,750.71) CN6.35@2512.86,714.14
PB6: CN6.30 U1.69 | length 2633.2
  Top Layer w10: v1@1355,1488.19 cw(c1355,1471.75) 1366.63,1483.37 cw(c1378.25,1495) v1@1361.81,1495 ; v1@1355,1491 v1(1355,1495) 1427,1423 1427,1370.37 1409.31,1352.67 1409.31,1265.64 U1.69@1408.53,1264.86 ; v1(1913,1710) 2012,1710 2080,1642 2080,1239 2080,1183 ; v1@1917.82,1705.18 cw(c1929.44,1693.56) 1929.44,1710 cw(c1929.44,1726.44) v1@1917.82,1714.82 ; 2080,1175 2080,1183 ; v1@2100.19,1145 ccw(c2083.75,1145) 2095.37,1156.63 ccw(c2107,1168.25) v1@2107,1151.81 ; v1(2107,1145) 2080,1172 2080,1183
  Bottom Layer w10: v1@1350.18,1499.82 ccw(c1338.56,1511.44) 1355,1511.44 ccw(c1371.44,1511.44) v1@1359.82,1499.82 ; v1(1355,1495) 1355,1555 1454,1654 1744,1654 1800,1710 v1(1913,1710) ; v1@1908.18,1705.18 ccw(c1896.56,1693.56) 1896.56,1710 ccw(c1896.56,1726.44) v1@1908.18,1714.82 ; v1@2107,1138.19 cw(c2107,1121.75) 2118.63,1133.37 cw(c2130.25,1145) v1@2113.81,1145 ; v1(2107,1145) 2249,1003 2392,1003 2446.58,948.42 2576.25,948.42 2626.83,999 CN6.30@2628,999 ; 2591.72,963.89 cw(c2624.95,930.66) CN6.30@2627.05,977.6 ; 2592.59,964.75 ccw(c2558.79,998.55) CN6.30@2606.58,998.86 ; CN6.30@2596.58,998.79 cw(c2525.18,998.33) 2575.67,947.84 cw(c2623.58,899.93) CN6.30@2626.6,967.61
PB7: CN1.29 U1.70 | length 2506.2
  Top Layer w10: v3@87,1242 87,1060 CN1.29@148,999 ; CN1.29@116.58,999 ccw(c40.73,999) 94.37,1052.63 ccw(c148,1106.27) CN1.29@148,1030.42 ; CN1.29@126.58,999 ccw(c74.88,999) 111.44,1035.56 ccw(c148,1072.12) CN1.29@148,1020.42 ; v1@857.18,1641.18 cw(c845.56,1629.56) 862,1629.56 cw(c878.44,1629.56) v1@866.82,1641.18 ; v1(862,1646) 862,1618 952,1528 1284.09,1528 1407,1405.09 1407,1375.82 1388.84,1357.67 U1.70@1388.84,1264.86
  Bottom Layer w10: v3(87,1243) 87,1529 107.58,1549.58 174.58,1549.58 198,1573 198,1626 221.58,1649.58 301.58,1649.58 342,1690 394,1690 818,1690 v1(862,1646) ; v1@855.19,1646 ccw(c838.75,1646) 850.37,1657.63 ccw(c862,1669.25) v1@862,1652.81
PB8: CN4.10 CN6.11 R22.1 U1.71 | length 5221.6
  Top Layer w10: U1.71@1369.16,1264.86 1369.16,1366.16 1379,1376 v1(1379,1398) ; v1@1374.18,1393.18 cw(c1362.56,1381.56) 1379,1381.56 cw(c1395.44,1381.56) v1@1383.82,1393.18 ; v1@2288,2281.19 cw(c2288,2264.75) 2299.63,2276.37 cw(c2311.25,2288) v1@2294.81,2288 ; v1(2288,2288) 2328,2248 2328,1975 CN4.10@2336,1967 ; CN4.10@2306.78,1994.22 ccw(c2255.57,2045.43) 2328,2045.43 ; CN4.10@2313.86,1987.14 ccw(c2279.71,2021.29) 2328,2021.29 ; 2328,2026.12 ccw(c2383.12,2026.12) CN4.10@2344.14,1987.14 ; 2328,2050.26 ccw(c2407.26,2050.26) CN4.10@2351.22,1994.22
  Bottom Layer w10: R22.1@807,304 879,304 927,352 927,554 543,938 543,1129 646,1232 646,1311 715,1380 979,1380 1035,1324 1149,1324 1223,1398 v1@1377,1398 ; R22.1@815.84,296.16 cw(c834.76,277.24) 834.76,304 ; R22.1@815.84,313.84 ccw(c839.59,337.59) 839.59,304 ; v1@1374.18,1393.18 ccw(c1362.56,1381.56) 1362.56,1398 ccw(c1362.56,1414.44) v1@1374.18,1402.82 ; v1(1379,1398) 1446,1398 1525.5,1477.5 1525.5,1517.5 1549,1541 1617,1541 1932,1541 1959,1568 1959,2108 2139,2288 v1(2288,2288) ; v1@1383.82,1393.18 cw(c1395.44,1381.56) 1395.44,1398 cw(c1395.44,1414.44) v1@1383.82,1402.82 ; v1@2283.18,2283.18 ccw(c2271.56,2271.56) 2271.56,2288 ccw(c2271.56,2304.44) v1@2283.18,2292.82 ; CN4.10@2328,1970 2457,1970 CN6.11@2528,1899 CN6.11@2523,1899 ; CN4.10@2344.14,1956.86 cw(c2375.88,1925.12) 2375.88,1970 ; CN4.10@2344.14,1987.14 ccw(c2385.53,2028.53) 2385.53,1970 ; CN4.10@2351.22,1949.78 cw(c2400.02,1900.98) 2400.02,1970 ; CN4.10@2351.22,1994.22 ccw(c2409.68,2052.68) 2409.68,1970 ; CN6.11@2496.58,1899 ccw(c2420.73,1899) 2474.37,1952.63 ccw(c2528,2006.27) CN6.11@2528,1930.42 ; CN6.11@2506.58,1899 ccw(c2454.88,1899) 2491.44,1935.56 ccw(c2528,1972.12) CN6.11@2528,1920.42
PB9: CN4.9 CN6.13 R23.1 U1.72 | length 5243.1
  Top Layer w10: v1@1349.18,1418.18 cw(c1337.1,1406.1) 1354.19,1406.1 ; U1.72@1349.47,1264.86 1349.47,1379.47 1354.19,1384.19 v1@1354.19,1420.81 ; 1354.19,1407.01 cw(c1369.99,1407.01) v1@1358.82,1418.18 ; CN4.9@2329,1872 2408,1951 2408,2083 2357,2134 2357,2273 v1(2342,2288) ; CN4.9@2329,1893.42 ccw(c2329,1945.12) 2365.56,1908.56 ccw(c2402.12,1872) CN4.9@2350.42,1872 ; CN4.9@2329,1903.42 ccw(c2329,1979.27) 2382.63,1925.63 ccw(c2436.27,1872) CN4.9@2360.42,1872 ; v1@2342,2281.19 cw(c2342,2264.75) 2353.63,2276.37 cw(c2365.25,2288) v1@2348.81,2288
  Bottom Layer w10: R23.1@798.16,500.84 ccw(c776.82,522.18) 807,522.18 ccw(c837.18,522.18) R23.1@815.84,500.84 ; R23.1@807,491 R23.1@807,492 807,628 516,919 516,1144 616,1244 616,1336 695,1415 989,1415 1054,1350 1141,1350 1214,1423 v1(1354,1423) ; v1@1349.18,1418.18 ccw(c1337.56,1406.56) 1337.56,1423 ccw(c1337.56,1439.44) v1@1349.18,1427.82 ; v1@1354,1421 1355.81,1422.81 1432.81,1422.81 1501,1491 1501,1538 1527,1564 1910,1564 1938,1592 1938,2142 2110,2314 2236,2314 ; v1@1358.82,1418.18 cw(c1369.99,1407.01) 1369.99,1422.81 ; v1@1358.82,1427.82 ccw(c1370.9,1439.9) 1370.9,1422.81 ; 2246,2314 2236,2314 ; 2289,2314 2273,2314 ; CN4.9@2328,1890 CN4.9@2335,1890 ; CN4.9@2329,1872 2455,1872 CN6.13@2528,1799 CN6.13@2512,1799 ; v1@2335.19,2288 ccw(c2318.75,2288) 2330.37,2299.63 ccw(c2342,2311.25) v1@2342,2294.81 ; v1(2342,2288) 2316,2314 2273,2314 ; CN4.9@2344.14,1856.86 cw(c2380.71,1820.29) 2380.71,1872 cw(c2380.71,1923.71) CN4.9@2344.14,1887.14 ; CN4.9@2351.22,1849.78 cw(c2404.85,1796.15) 2404.85,1872 cw(c2404.85,1947.85) CN4.9@2351.22,1894.22 ; CN6.13@2496.58,1799 ccw(c2420.73,1799) 2474.37,1852.63 ccw(c2528,1906.27) CN6.13@2528,1830.42 ; CN6.13@2506.58,1799 ccw(c2454.88,1799) 2491.44,1835.56 ccw(c2528,1872.12) CN6.13@2528,1820.42 ; 2236,2314 2273,2314
PB10: R20.2 U1.38 | length 1782.5
  Top Layer w10: v1@858,342.19 cw(c858,325.75) 869.63,337.37 cw(c881.25,349) v1@864.81,349 ; v1(858,349) 966,241 1663,241 1736,314 v1(1736,377) ; U1.38@1526.64,747.14 1526.64,681.36 1578,630 1632,630 v1(1669,593) ; v1@1662.19,593 ccw(c1645.75,593) 1657.37,604.63 ccw(c1669,616.25) v1@1669,599.81 ; v1@1731.18,372.18 cw(c1719.56,360.56) 1736,360.56 cw(c1752.44,360.56) v1@1740.82,372.18
  Bottom Layer w10: R20.2@805,402 v1@858.5,348.5 ; R20.2@807,390.5 cw(c807,367.57) 823.22,383.78 ; R20.2@819.5,403 ccw(c856.92,403) 830.46,376.54 ; v1@851.19,349 ccw(c834.75,349) 846.37,360.63 ccw(c858,372.25) v1@858,355.81 ; v1@1669,586.19 cw(c1669,569.75) 1680.63,581.37 cw(c1692.25,593) v1@1675.81,593 ; v1(1669,593) 1736,526 v1(1736,377) ; v1@1731.18,381.82 ccw(c1719.56,393.44) 1736,393.44 ccw(c1752.44,393.44) v1@1740.82,381.82
PB11: R21.2 U1.39 | length 1897.2
  Top Layer w10: v1(863,197) 1693,197 1776,280 v1(1776,377) ; v1@867.82,192.18 cw(c879.44,180.56) 879.44,197 cw(c879.44,213.44) v1@867.82,201.82 ; U1.39@1546.32,747.14 1546.32,703.68 1594,656 1648,656 v1(1672,632) v1@1673,631 ; v1@1665.19,632 ccw(c1648.75,632) 1660.37,643.63 ccw(c1672,655.25) v1@1672,638.81 ; v1@1771.18,372.18 cw(c1759.56,360.56) 1776,360.56 cw(c1792.44,360.56) v1@1780.82,372.18
  Bottom Layer w10: R21.2@800.49,213.28 ccw(c828.54,229.31) 828.54,197 ; R21.2@805,216 824,197 v1(863,197) cw(c863,248.99) R21.2@817.85,223.2 ; R21.2@809.17,218.24 ccw(c845.77,239.15) 845.77,197 ; v1@858.18,192.18 ccw(c846.56,180.56) 846.56,197 ccw(c846.56,213.44) v1@858.18,201.82 ; v1@1671.5,632.5 v1(1672,632) 1776,528 v1(1776,377) ; v1@1672,625.19 cw(c1672,608.75) 1683.63,620.37 cw(c1695.25,632) v1@1678.81,632 ; v1@1771.18,381.82 ccw(c1759.56,393.44) 1776,393.44 ccw(c1792.44,393.44) v1@1780.82,381.82
PB12: CN6.38 U1.40 | length 1600.4
  Top Layer w10: U1.40@1566.01,747.14 1566.15,747 1642,747 1681,786 1890,786 2214,462 2214,433 2284.42,362.58 2377.58,362.58 2404,389 2404,436 2462,494 2462,529 2482,549 2578,549 ; CN6.38@2596.62,597.4 cw(c2532.85,594.16) 2578,549 ; CN6.38@2606.61,597.91 cw(c2563.13,595.7) 2593.92,564.92 cw(c2624.7,534.13) CN6.38@2626.91,577.61 ; CN6.38@2626.4,567.62 ccw(c2623.16,503.85) 2578,549 ; CN6.38@2631,596 CN6.38@2628,599 2578,549
PB13: CN6.36 U1.41 | length 1505
  Top Layer w10: U1.41@1637.86,818.99 1906.01,818.99 2262.42,462.58 2350,462.58 ; 2370.58,462.58 2350,462.58 ; 2470.58,648.58 2477,648.58 ; CN6.36@2596.61,697.6 cw(c2531.49,694.68) 2577.59,648.59 ; CN6.36@2606.6,698.04 cw(c2562.21,696.06) 2593.63,664.63 cw(c2625.06,633.21) CN6.36@2627.04,677.6 ; CN6.36@2626.6,667.61 ccw(c2623.68,602.49) 2577.59,648.59 ; CN6.36@2628,699 2577.58,648.58 ; 2350,462.58 2372.58,462.58 2428,518 2428,621 2455.58,648.58 2477,648.58 ; 2477,648.58 2577.58,648.58
PB14: CN5.7 CN6.33 U1.42 | length 1950.4
  Top Layer w10: U1.42@1637.86,838.68 1815,838.68 ; 1835.32,838.68 1815,838.68 ; 2306.7,562 2214,562 1937.32,838.68 1815,838.68 ; 2306.7,562.58 2370.58,562.58 2395,587 2395,643 2471,719 2471,781 2489,799 CN6.33@2528,799 ; 2470.83,780.83 cw(c2502.28,749.37) CN6.33@2522.75,788.86 ; 2480.49,790.49 cw(c2508.87,762.1) CN6.33@2527.35,797.74 ; 2490.15,800.15 cw(c2515.47,774.83) CN6.33@2531.95,806.62
  Bottom Layer w10: CN5.7@2328,812 2418,812 2431,799 CN6.33@2528,799 ; CN5.7@2344.14,796.86 cw(c2380.71,760.29) 2380.71,812 cw(c2380.71,863.71) CN5.7@2344.14,827.14 ; CN5.7@2351.22,789.78 cw(c2404.85,736.15) 2404.85,812 cw(c2404.85,887.85) CN5.7@2351.22,834.22 ; CN6.33@2505.78,776.78 ccw(c2452.15,723.15) 2452.15,799 ccw(c2452.15,874.85) CN6.33@2505.78,821.22 ; CN6.33@2512.86,783.86 ccw(c2476.29,747.29) 2476.29,799 ccw(c2476.29,850.71) CN6.33@2512.86,814.14
PB15: CN6.34 U1.43 | length 1430.5
  Top Layer w10: U1.43@1637.86,858.36 1941,858.36 ; 1960,858.36 1941,858.36 ; 2495.42,848.42 2514,848.42 ; CN6.34@2596.64,800.87 ccw(c2534.73,804.56) 2578.58,848.42 ; CN6.34@2606.62,800.28 ccw(c2564.42,802.79) 2594.31,832.69 ccw(c2624.21,862.58) CN6.34@2626.72,820.38 ; CN6.34@2626.13,830.36 cw(c2622.44,892.27) 2578.58,848.42 ; CN6.34@2628,799 2578.58,848.42 ; 1941,858.36 1967.64,858.36 2163.42,662.58 2362.58,662.58 2432,732 2432,814 2466.42,848.42 2514,848.42 ; 2514,848.42 2578.58,848.42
